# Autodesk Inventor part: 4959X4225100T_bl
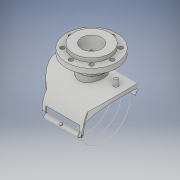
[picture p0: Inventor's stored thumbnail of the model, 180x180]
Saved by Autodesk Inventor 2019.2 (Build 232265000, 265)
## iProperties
Created: 2020-06
Part Number: 4959X4225100T_bl
Material: Generic
Description: Plasson Flanged Branch Saddle 225x100
Document SubType Name: Modeling
Designer: KIM
Density: 1 g/cm^3
Appearance: Default
Author: KIM
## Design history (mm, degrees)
derived "4959X4.ipt"
feature "Solid1::4959X4.ipt" dims "ScaleForDerivedMember" = 10
feature "Solid2::4959X4.ipt" dims "ScaleForDerivedMember" = 10
tag "TaggingFeature1"
body "Solid1"
body "Solid2"
other parameters: "d0" = 295 [user parameter], "d2" = 225 [user parameter], "d7" = 87 [user parameter], "d10" = 0.5 [user parameter], "d11" = 1 [user parameter], "d13" = 16 [user parameter], "d14" = 8 [user parameter], "d16" = 10 deg [user parameter], "d17" = 10 deg [user parameter], "d19" = 0 [user parameter], "d23" = 0 [user parameter], "d26" = 0 [user parameter], "d27" = 177 [user parameter], "d28" = 0 [user parameter], "d29" = 147.5 [user parameter], "d30" = 0 [user parameter], "d31" = 1 [user parameter], "d32" = 1 [user parameter], "d33" = 19.2 [user parameter], "d34" = 9.6 [user parameter], "d35" = 45 deg [user parameter], "d36" = 147.5 [user parameter], "d37" = 0 [user parameter], "d38" = 5 [user parameter], "d39" = 85 deg [user parameter], "d41" = 16 [user parameter], "d42" = 107.27273 [user parameter], "d49" = 3 [user parameter], "d50" = 6 [user parameter], "d51" = 5 [user parameter], "d54" = 0 [user parameter], "d57" = 35 deg [user parameter], "d60" = 18.4375 [user parameter], "d61" = 1 [user parameter], "d62" = 90 deg [user parameter], "d63" = 2 [user parameter], "d64" = 0 [user parameter], "d65" = 0 [user parameter], "d68" = 36.875 [user parameter], "d70" = 0.57711 [user parameter], "d71" = 10 deg [user parameter], "d73" = 5.25 [user parameter], "d75" = 22 [user parameter], "d77" = 89.25 [user parameter], "d78" = 105 [user parameter], "d79" = 158 [user parameter], "d80" = 1 [user parameter], "d81" = 104.4 [user parameter], "d82" = 121.8 [user parameter], "d83" = 1 [user parameter], "d84" = 16.5 [user parameter], "d87" = 18 [user parameter], "d95" = 360 deg [user parameter], "d" = 225 [user parameter], "d_h" = 158 [user parameter], "B" = 272 [user parameter], "L" = 295 [user parameter], "LS" = 105 [user parameter], "Dt" = 16 [user parameter], "di" = 87 [user parameter], "s_" = 18 [user parameter], "t" = 22 [user parameter], "d72" = 15 [user parameter]
